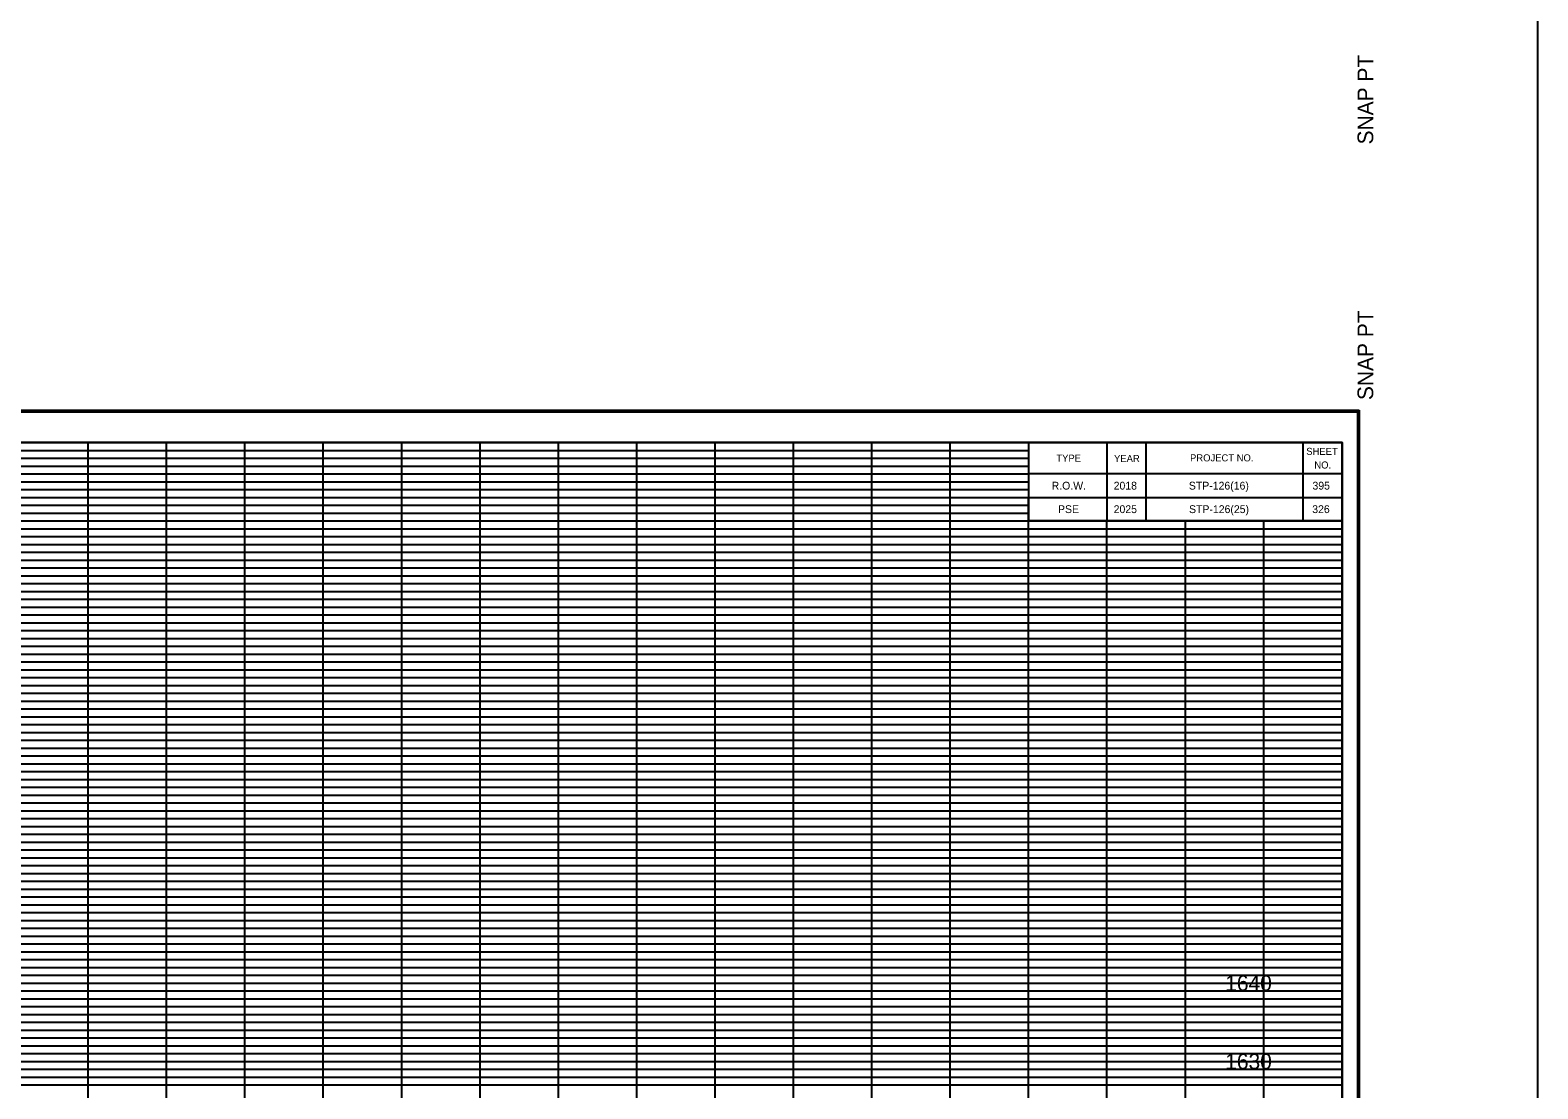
# Model space of a CAD drawing. Extents: x 955 to 1375, y 1248 to 3657.
# Drawn here: x 1152.6 to 1345, y 2207.5 to 2342.7 of the extents above; entities that cross this region are included whole.
import ezdxf

# ---------------------------------------------------------------- set-up
doc = ezdxf.new("R2010")
doc.units = 0
for name, color, linetype in [('DESIGN - SCRATCH - User 1', 7, 'Continuous'), ('DESIGN - SHEET - Corner Text', 7, 'Continuous'), ('DESIGN - SHEET - Light Grid', 7, 'Continuous'), ('DESIGN - SHEET - Linework', 7, 'Continuous'), ('DESIGN - SHEET - Plot Shape', 7, 'Continuous'), ('DESIGN - TYPICAL - Text', 7, 'Continuous'), ('DESIGN - UTILITIES - Cable (Overhead) with Text', 7, 'Continuous'), ('SURVEY - NON-TRANSPORTATION - Features Text', 7, 'Continuous')]:
    doc.layers.add(name, color=color, linetype=linetype)

# ---------------------------------------------------------------- blocks, each defined once
blk = doc.blocks.new('XSTSHT')
at = {"layer": 'DESIGN - SCRATCH - User 1'}
for p, q in [((28.5, 20.45), (28.5, 20.45)), ((29.24, 20.45), (29.24, 20.45)), ((30.49, 20.45), (30.49, 20.45)), ((31.74, 20.45), (31.74, 20.45)), ((28.5, 20.15), (28.5, 20.15)), ((29.24, 20.15), (29.24, 20.15)), ((30.49, 20.15), (30.49, 20.15)), ((31.74, 20.15), (31.74, 20.15))]:
    blk.add_line(p, q, dxfattribs=at)
at = {"layer": 'DESIGN - SHEET - Light Grid'}
for p, q in [((8, 20.9), (16, 20.9)), ((8, 20.8), (16, 20.8)), ((16, 20.9), (24, 20.9)), ((16, 20.8), (24, 20.8)), ((24, 20.9), (28, 20.9)), ((24, 20.8), (28, 20.8)), ((8, 20.7), (16, 20.7)), ((8, 20.6), (16, 20.6)), ((16, 20.7), (24, 20.7)), ((16, 20.6), (24, 20.6)), ((24, 20.7), (28, 20.7)), ((24, 20.6), (28, 20.6)), ((8, 20.5), (16, 20.5)), ((8, 20.4), (16, 20.4)), ((16, 20.5), (24, 20.5)), ((16, 20.4), (24, 20.4)), ((24, 20.5), (28, 20.5)), ((24, 20.4), (28, 20.4)), ((8, 20.3), (16, 20.3)), ((16, 20.3), (24, 20.3)), ((24, 20.3), (28, 20.3)), ((8, 20.2), (16, 20.2)), ((8, 20.1), (16, 20.1)), ((16, 20.2), (24, 20.2)), ((16, 20.1), (24, 20.1)), ((24, 20.2), (28, 20.2)), ((24, 20.1), (28, 20.1)), ((8, 19.9), (16, 19.9)), ((16, 19.9), (24, 19.9)), ((24, 19.9), (32, 19.9)), ((8, 19.8), (16, 19.8)), ((8, 19.7), (16, 19.7)), ((16, 19.8), (24, 19.8)), ((16, 19.7), (24, 19.7)), ((24, 19.8), (32, 19.8)), ((24, 19.7), (32, 19.7)), ((8, 19.6), (16, 19.6)), ((8, 19.5), (16, 19.5)), ((16, 19.6), (24, 19.6)), ((16, 19.5), (24, 19.5)), ((24, 19.6), (32, 19.6)), ((24, 19.5), (32, 19.5)), ((8, 19.4), (16, 19.4)), ((8, 19.3), (16, 19.3)), ((16, 19.4), (24, 19.4)), ((16, 19.3), (24, 19.3)), ((24, 19.4), (32, 19.4)), ((24, 19.3), (32, 19.3)), ((8, 19.2), (16, 19.2)), ((8, 19.1), (16, 19.1)), ((16, 19.2), (24, 19.2)), ((16, 19.1), (24, 19.1)), ((24, 19.2), (32, 19.2)), ((24, 19.1), (32, 19.1)), ((8, 18.9), (16, 18.9)), ((16, 18.9), (24, 18.9)), ((24, 18.9), (32, 18.9)), ((8, 18.8), (16, 18.8)), ((8, 18.7), (16, 18.7)), ((16, 18.8), (24, 18.8)), ((16, 18.7), (24, 18.7)), ((24, 18.8), (32, 18.8)), ((24, 18.7), (32, 18.7)), ((8, 18.6), (16, 18.6)), ((8, 18.5), (16, 18.5)), ((16, 18.6), (24, 18.6)), ((16, 18.5), (24, 18.5)), ((24, 18.6), (32, 18.6)), ((24, 18.5), (32, 18.5)), ((8, 18.4), (16, 18.4)), ((8, 18.3), (16, 18.3)), ((16, 18.4), (24, 18.4)), ((16, 18.3), (24, 18.3)), ((24, 18.4), (32, 18.4)), ((24, 18.3), (32, 18.3)), ((8, 18.2), (16, 18.2)), ((8, 18.1), (16, 18.1)), ((16, 18.2), (24, 18.2)), ((16, 18.1), (24, 18.1)), ((24, 18.2), (32, 18.2)), ((24, 18.1), (32, 18.1)), ((8, 17.9), (16, 17.9)), ((16, 17.9), (24, 17.9)), ((24, 17.9), (32, 17.9)), ((8, 17.8), (16, 17.8)), ((8, 17.7), (16, 17.7)), ((16, 17.8), (24, 17.8)), ((16, 17.7), (24, 17.7)), ((24, 17.8), (32, 17.8)), ((24, 17.7), (32, 17.7)), ((8, 17.6), (16, 17.6)), ((16, 17.6), (24, 17.6)), ((24, 17.6), (32, 17.6)), ((8, 17.5), (16, 17.5)), ((8, 17.4), (16, 17.4)), ((16, 17.5), (24, 17.5)), ((16, 17.4), (24, 17.4)), ((24, 17.5), (32, 17.5)), ((24, 17.4), (32, 17.4)), ((8, 17.3), (16, 17.3)), ((8, 17.2), (16, 17.2)), ((16, 17.3), (24, 17.3)), ((16, 17.2), (24, 17.2)), ((24, 17.3), (32, 17.3)), ((24, 17.2), (32, 17.2)), ((8, 17.1), (16, 17.1)), ((16, 17.1), (24, 17.1)), ((24, 17.1), (32, 17.1)), ((8, 16.9), (16, 16.9)), ((8, 16.8), (16, 16.8)), ((16, 16.9), (24, 16.9)), ((16, 16.8), (24, 16.8)), ((24, 16.9), (32, 16.9)), ((24, 16.8), (32, 16.8)), ((8, 16.7), (16, 16.7)), ((8, 16.6), (16, 16.6)), ((16, 16.7), (24, 16.7)), ((16, 16.6), (24, 16.6)), ((24, 16.7), (32, 16.7)), ((24, 16.6), (32, 16.6)), ((8, 16.5), (16, 16.5)), ((8, 16.4), (16, 16.4)), ((16, 16.5), (24, 16.5)), ((16, 16.4), (24, 16.4)), ((24, 16.5), (32, 16.5)), ((24, 16.4), (32, 16.4)), ((8, 16.3), (16, 16.3)), ((8, 16.2), (16, 16.2)), ((16, 16.3), (24, 16.3)), ((16, 16.2), (24, 16.2)), ((24, 16.3), (32, 16.3)), ((24, 16.2), (32, 16.2)), ((8, 16.1), (16, 16.1)), ((16, 16.1), (24, 16.1)), ((24, 16.1), (32, 16.1)), ((8, 15.9), (16, 15.9)), ((8, 15.8), (16, 15.8)), ((16, 15.9), (24, 15.9)), ((16, 15.8), (24, 15.8)), ((24, 15.9), (32, 15.9)), ((24, 15.8), (32, 15.8)), ((8, 15.7), (16, 15.7)), ((8, 15.6), (16, 15.6)), ((16, 15.7), (24, 15.7)), ((16, 15.6), (24, 15.6)), ((24, 15.7), (32, 15.7)), ((24, 15.6), (32, 15.6)), ((8, 15.5), (16, 15.5)), ((8, 15.4), (16, 15.4)), ((16, 15.5), (24, 15.5)), ((16, 15.4), (24, 15.4)), ((24, 15.5), (32, 15.5)), ((24, 15.4), (32, 15.4)), ((8, 15.3), (16, 15.3)), ((8, 15.2), (16, 15.2)), ((16, 15.3), (24, 15.3)), ((16, 15.2), (24, 15.2)), ((24, 15.3), (32, 15.3)), ((24, 15.2), (32, 15.2)), ((8, 15.1), (16, 15.1)), ((16, 15.1), (24, 15.1)), ((24, 15.1), (32, 15.1)), ((8, 14.9), (16, 14.9)), ((16, 14.9), (24, 14.9)), ((24, 14.9), (32, 14.9)), ((8, 14.8), (16, 14.8)), ((8, 14.7), (16, 14.7)), ((16, 14.8), (24, 14.8)), ((16, 14.7), (24, 14.7)), ((24, 14.8), (32, 14.8)), ((24, 14.7), (32, 14.7)), ((8, 14.6), (16, 14.6)), ((8, 14.5), (16, 14.5)), ((16, 14.6), (24, 14.6)), ((16, 14.5), (24, 14.5)), ((24, 14.6), (32, 14.6)), ((24, 14.5), (32, 14.5)), ((8, 14.4), (16, 14.4)), ((8, 14.3), (16, 14.3)), ((16, 14.4), (24, 14.4)), ((16, 14.3), (24, 14.3)), ((24, 14.4), (32, 14.4)), ((24, 14.3), (32, 14.3)), ((8, 14.2), (16, 14.2)), ((8, 14.1), (16, 14.1)), ((16, 14.2), (24, 14.2)), ((16, 14.1), (24, 14.1)), ((24, 14.2), (32, 14.2)), ((24, 14.1), (32, 14.1)), ((8, 13.9), (16, 13.9)), ((16, 13.9), (24, 13.9)), ((24, 13.9), (32, 13.9)), ((8, 13.8), (16, 13.8)), ((8, 13.7), (16, 13.7)), ((16, 13.8), (24, 13.8)), ((16, 13.7), (24, 13.7)), ((24, 13.8), (32, 13.8)), ((24, 13.7), (32, 13.7)), ((8, 13.6), (16, 13.6)), ((8, 13.5), (16, 13.5)), ((16, 13.6), (24, 13.6)), ((16, 13.5), (24, 13.5)), ((24, 13.6), (32, 13.6)), ((24, 13.5), (32, 13.5)), ((8, 13.4), (16, 13.4)), ((8, 13.3), (16, 13.3)), ((16, 13.4), (24, 13.4)), ((16, 13.3), (24, 13.3)), ((24, 13.4), (32, 13.4)), ((24, 13.3), (32, 13.3)), ((8, 13.2), (16, 13.2)), ((8, 13.1), (16, 13.1)), ((16, 13.2), (24, 13.2)), ((16, 13.1), (24, 13.1)), ((24, 13.2), (32, 13.2)), ((24, 13.1), (32, 13.1)), ((8, 12.9), (16, 12.9)), ((16, 12.9), (24, 12.9)), ((24, 12.9), (32, 12.9)), ((8, 12.8), (16, 12.8)), ((16, 12.8), (24, 12.8)), ((24, 12.8), (32, 12.8))]:
    blk.add_line(p, q, dxfattribs=at)
at = {"layer": 'DESIGN - SHEET - Linework'}
for p, q in [((-1.823, 21.414), (32.217, 21.414)), ((32.217, 21.414), (32.217, -0.414)), ((16, 0), (16, 21)), ((17, 0), (17, 21)), ((18, 0), (18, 21)), ((19, 0), (19, 21)), ((20, 0), (20, 21)), ((21, 0), (21, 21)), ((22, 0), (22, 21)), ((23, 0), (23, 21)), ((24, 0), (24, 21)), ((25, 0), (25, 21)), ((26, 0), (26, 21)), ((27, 0), (27, 21)), ((0, 20), (28, 20)), ((28, 0), (28, 20)), ((29, 0), (29, 20)), ((30, 0), (30, 20)), ((31, 0), (31, 20)), ((0, 19), (32, 19)), ((0, 18), (32, 18)), ((0, 17), (32, 17)), ((0, 16), (32, 16)), ((0, 15), (32, 15)), ((0, 14), (32, 14)), ((0, 13), (32, 13))]:
    blk.add_line(p, q, dxfattribs=at)
for points in [[(0, 21), (0, 0), (32, 0), (32, 21), (0, 21)], [(28, 21), (28, 20), (32, 20), (32, 21), (31.5, 21), (31.5, 20), (29.5, 20), (29.5, 21), (29, 21), (29, 20), (32, 20), (28, 20), (28, 20.3), (32, 20.3), (32, 20.6), (28, 20.6)]]:
    blk.add_lwpolyline(points, dxfattribs=at)
at = {"layer": 'DESIGN - SHEET - Plot Shape'}
for points in [[(-1.803, 21.394), (32.197, 21.394), (32.197, -0.394), (-1.803, -0.394)], [(-0.85, 21), (32, 21), (32, -0.25), (-0.85, -0.25)]]:
    blk.add_lwpolyline(points, close=True, dxfattribs=at)
at = {"layer": 'DESIGN - SHEET - Corner Text'}
for s, p in [('  SNAP PT', (32.397, 21.394)), ('SNAP PT  ', (32.397, -2.194))]:
    blk.add_text(s, height=0.2, rotation=90, dxfattribs=at).set_placement(p)
for s, p in [('TYPE', (28.354, 20.756)), ('YEAR', (29.09, 20.752)), ('PROJECT NO.', (30.06, 20.76)), ('SHEET', (31.543, 20.843)), ('NO.', (31.646, 20.669))]:
    blk.add_text(s, height=0.09, dxfattribs=at).set_placement(p)

msp = doc.modelspace()

# ---------------------------------------------------------------- linework, layer by layer
at = {"layer": 'DESIGN - SHEET - Plot Shape'}
msp.add_lwpolyline([(991.5, 2077.5), (1320, 2077.5), (1320, 2290), (991.5, 2290)], close=True, dxfattribs=at)
at = {"layer": 'SURVEY - NON-TRANSPORTATION - Features Text'}
msp.add_lwpolyline([(955.41, 1505.76), (1344.98, 1505.76), (1344.98, 3398.01), (955.41, 3398.01)], close=True, dxfattribs=at)

# ---------------------------------------------------------------- block references
at = {"layer": 'DESIGN - UTILITIES - Cable (Overhead) with Text', "xscale": 10, "yscale": 10}
for p in [(1000, 2350), (1000, 2080)]:
    msp.add_blockref('XSTSHT', p, dxfattribs=at)

# ---------------------------------------------------------------- texts
at = {"layer": 'DESIGN - SHEET - Corner Text'}
for s, p in [('R.O.W.', (1282.94, 2284)), ('2018', (1290.85, 2284)), ('STP-126(16)', (1300.45, 2284)), ('395', (1316.22, 2284)), ('PSE', (1283.75, 2281)), ('2025', (1290.85, 2281)), ('STP-126(25)', (1300.47, 2281)), ('326', (1316.19, 2281))]:
    msp.add_text(s, height=1, dxfattribs=at).set_placement(p)
at = {"layer": 'DESIGN - TYPICAL - Text'}
for s, p in [('     1640     ', (1301.37, 2220)), ('     1630     ', (1301.37, 2210))]:
    msp.add_text(s, height=2, dxfattribs=at).set_placement(p)

doc.saveas('drawing.dxf')
